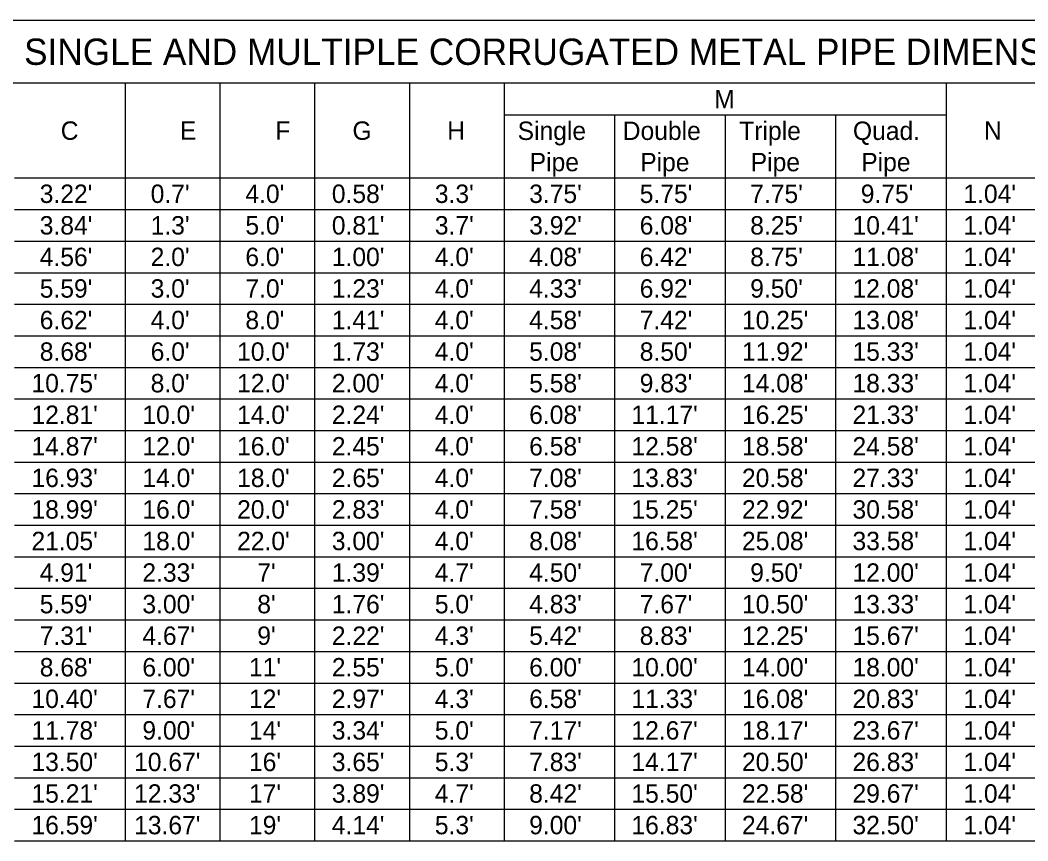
# Model space of a CAD drawing. Extents: x -1.3 to 14.4, y 0 to 6.5.
# Drawn here: x 4.481 to 8.31, y 3.39 to 6.51 of the extents above; entities that cross this region are included whole.
import ezdxf

# ---------------------------------------------------------------- set-up
doc = ezdxf.new("R2010")
doc.units = 0
doc.layers.add('TextNotes', color=7, linetype='Continuous')
doc.layers.add('TextTables', color=7, linetype='Continuous')

msp = doc.modelspace()

# ---------------------------------------------------------------- linework, layer by layer
at = {"layer": 'TextTables'}
msp.add_line((2, 6.51), (13.4, 6.51), dxfattribs=at)
for points in [[(13.4, 6.27), (11.72, 6.27), (10.04, 6.27), (8.36, 6.27), (8, 6.27), (6.32, 6.27), (5.96, 6.27), (5.6, 6.27), (5.24, 6.27), (4.88, 6.27), (4.46, 6.27), (3.98, 6.27), (3.56, 6.27), (3.14, 6.27), (2.84, 6.27), (2.54, 6.27), (2.24, 6.27), (2, 6.27)], [(4.88, 6.27), (4.88, 5.91), (4.88, 5.79), (4.88, 5.67), (4.88, 5.55), (4.88, 5.43), (4.88, 5.31), (4.88, 5.19), (4.88, 5.07), (4.88, 4.95), (4.88, 4.83), (4.88, 4.71), (4.88, 4.59), (4.88, 4.47), (4.88, 4.35), (4.88, 4.23), (4.88, 4.11), (4.88, 3.99), (4.88, 3.87), (4.88, 3.75), (4.88, 3.63), (4.88, 3.51), (4.88, 3.39)], [(5.24, 6.27), (5.24, 5.91), (5.24, 5.79), (5.24, 5.67), (5.24, 5.55), (5.24, 5.43), (5.24, 5.31), (5.24, 5.19), (5.24, 5.07), (5.24, 4.95), (5.24, 4.83), (5.24, 4.71), (5.24, 4.59), (5.24, 4.47), (5.24, 4.35), (5.24, 4.23), (5.24, 4.11), (5.24, 3.99), (5.24, 3.87), (5.24, 3.75), (5.24, 3.63), (5.24, 3.51), (5.24, 3.39)], [(5.6, 6.27), (5.6, 5.91), (5.6, 5.79), (5.6, 5.67), (5.6, 5.55), (5.6, 5.43), (5.6, 5.31), (5.6, 5.19), (5.6, 5.07), (5.6, 4.95), (5.6, 4.83), (5.6, 4.71), (5.6, 4.59), (5.6, 4.47), (5.6, 4.35), (5.6, 4.23), (5.6, 4.11), (5.6, 3.99), (5.6, 3.87), (5.6, 3.75), (5.6, 3.63), (5.6, 3.51), (5.6, 3.39)], [(5.96, 6.27), (5.96, 5.91), (5.96, 5.79), (5.96, 5.67), (5.96, 5.55), (5.96, 5.43), (5.96, 5.31), (5.96, 5.19), (5.96, 5.07), (5.96, 4.95), (5.96, 4.83), (5.96, 4.71), (5.96, 4.59), (5.96, 4.47), (5.96, 4.35), (5.96, 4.23), (5.96, 4.11), (5.96, 3.99), (5.96, 3.87), (5.96, 3.75), (5.96, 3.63), (5.96, 3.51), (5.96, 3.39)], [(6.32, 6.27), (6.32, 6.15), (6.32, 5.91), (6.32, 5.79), (6.32, 5.67), (6.32, 5.55), (6.32, 5.43), (6.32, 5.31), (6.32, 5.19), (6.32, 5.07), (6.32, 4.95), (6.32, 4.83), (6.32, 4.71), (6.32, 4.59), (6.32, 4.47), (6.32, 4.35), (6.32, 4.23), (6.32, 4.11), (6.32, 3.99), (6.32, 3.87), (6.32, 3.75), (6.32, 3.63), (6.32, 3.51), (6.32, 3.39)], [(8, 6.27), (8, 6.15), (8, 5.91), (8, 5.79), (8, 5.67), (8, 5.55), (8, 5.43), (8, 5.31), (8, 5.19), (8, 5.07), (8, 4.95), (8, 4.83), (8, 4.71), (8, 4.59), (8, 4.47), (8, 4.35), (8, 4.23), (8, 4.11), (8, 3.99), (8, 3.87), (8, 3.75), (8, 3.63), (8, 3.51), (8, 3.39)], [(6.32, 6.15), (6.74, 6.15), (7.16, 6.15), (7.58, 6.15), (8, 6.15)], [(6.74, 6.15), (6.74, 5.91), (6.74, 5.79), (6.74, 5.67), (6.74, 5.55), (6.74, 5.43), (6.74, 5.31), (6.74, 5.19), (6.74, 5.07), (6.74, 4.95), (6.74, 4.83), (6.74, 4.71), (6.74, 4.59), (6.74, 4.47), (6.74, 4.35), (6.74, 4.23), (6.74, 4.11), (6.74, 3.99), (6.74, 3.87), (6.74, 3.75), (6.74, 3.63), (6.74, 3.51), (6.74, 3.39)], [(7.16, 6.15), (7.16, 5.91), (7.16, 5.79), (7.16, 5.67), (7.16, 5.55), (7.16, 5.43), (7.16, 5.31), (7.16, 5.19), (7.16, 5.07), (7.16, 4.95), (7.16, 4.83), (7.16, 4.71), (7.16, 4.59), (7.16, 4.47), (7.16, 4.35), (7.16, 4.23), (7.16, 4.11), (7.16, 3.99), (7.16, 3.87), (7.16, 3.75), (7.16, 3.63), (7.16, 3.51), (7.16, 3.39)], [(7.58, 6.15), (7.58, 5.91), (7.58, 5.79), (7.58, 5.67), (7.58, 5.55), (7.58, 5.43), (7.58, 5.31), (7.58, 5.19), (7.58, 5.07), (7.58, 4.95), (7.58, 4.83), (7.58, 4.71), (7.58, 4.59), (7.58, 4.47), (7.58, 4.35), (7.58, 4.23), (7.58, 4.11), (7.58, 3.99), (7.58, 3.87), (7.58, 3.75), (7.58, 3.63), (7.58, 3.51), (7.58, 3.39)], [(4.46, 5.91), (4.88, 5.91), (5.24, 5.91), (5.6, 5.91), (5.96, 5.91), (6.32, 5.91), (6.74, 5.91), (7.16, 5.91), (7.58, 5.91), (8, 5.91), (8.36, 5.91), (9.2, 5.91), (10.04, 5.91), (10.46, 5.91), (10.88, 5.91), (11.3, 5.91), (11.72, 5.91), (12.14, 5.91), (12.56, 5.91), (12.98, 5.91), (13.4, 5.91)], [(4.46, 5.79), (4.88, 5.79), (5.24, 5.79), (5.6, 5.79), (5.96, 5.79), (6.32, 5.79), (6.74, 5.79), (7.16, 5.79), (7.58, 5.79), (8, 5.79), (8.36, 5.79), (9.2, 5.79), (10.04, 5.79), (10.46, 5.79), (10.88, 5.79), (11.3, 5.79), (11.72, 5.79), (12.14, 5.79), (12.56, 5.79), (12.98, 5.79), (13.4, 5.79)], [(4.46, 5.67), (4.88, 5.67), (5.24, 5.67), (5.6, 5.67), (5.96, 5.67), (6.32, 5.67), (6.74, 5.67), (7.16, 5.67), (7.58, 5.67), (8, 5.67), (8.36, 5.67), (9.2, 5.67), (10.04, 5.67), (10.46, 5.67), (10.88, 5.67), (11.3, 5.67), (11.72, 5.67), (12.14, 5.67), (12.56, 5.67), (12.98, 5.67), (13.4, 5.67)], [(4.46, 5.55), (4.88, 5.55), (5.24, 5.55), (5.6, 5.55), (5.96, 5.55), (6.32, 5.55), (6.74, 5.55), (7.16, 5.55), (7.58, 5.55), (8, 5.55), (8.36, 5.55), (9.2, 5.55), (10.04, 5.55), (10.46, 5.55), (10.88, 5.55), (11.3, 5.55), (11.72, 5.55), (12.14, 5.55), (12.56, 5.55), (12.98, 5.55), (13.4, 5.55)], [(4.46, 5.43), (4.88, 5.43), (5.24, 5.43), (5.6, 5.43), (5.96, 5.43), (6.32, 5.43), (6.74, 5.43), (7.16, 5.43), (7.58, 5.43), (8, 5.43), (8.36, 5.43), (9.2, 5.43), (10.04, 5.43), (10.46, 5.43), (10.88, 5.43), (11.3, 5.43), (11.72, 5.43), (12.14, 5.43), (12.56, 5.43), (12.98, 5.43), (13.4, 5.43)], [(4.46, 5.31), (4.88, 5.31), (5.24, 5.31), (5.6, 5.31), (5.96, 5.31), (6.32, 5.31), (6.74, 5.31), (7.16, 5.31), (7.58, 5.31), (8, 5.31), (8.36, 5.31), (9.2, 5.31), (10.04, 5.31), (10.46, 5.31), (10.88, 5.31), (11.3, 5.31), (11.72, 5.31), (12.14, 5.31), (12.56, 5.31), (12.98, 5.31), (13.4, 5.31)], [(4.46, 5.19), (4.88, 5.19), (5.24, 5.19), (5.6, 5.19), (5.96, 5.19), (6.32, 5.19), (6.74, 5.19), (7.16, 5.19), (7.58, 5.19), (8, 5.19), (8.36, 5.19), (9.2, 5.19), (10.04, 5.19), (10.46, 5.19), (10.88, 5.19), (11.3, 5.19), (11.72, 5.19), (12.14, 5.19), (12.56, 5.19), (12.98, 5.19), (13.4, 5.19)], [(4.46, 5.07), (4.88, 5.07), (5.24, 5.07), (5.6, 5.07), (5.96, 5.07), (6.32, 5.07), (6.74, 5.07), (7.16, 5.07), (7.58, 5.07), (8, 5.07), (8.36, 5.07), (9.2, 5.07), (10.04, 5.07), (10.46, 5.07), (10.88, 5.07), (11.3, 5.07), (11.72, 5.07), (12.14, 5.07), (12.56, 5.07), (12.98, 5.07), (13.4, 5.07)], [(4.46, 4.95), (4.88, 4.95), (5.24, 4.95), (5.6, 4.95), (5.96, 4.95), (6.32, 4.95), (6.74, 4.95), (7.16, 4.95), (7.58, 4.95), (8, 4.95), (8.36, 4.95), (9.2, 4.95), (10.04, 4.95), (10.46, 4.95), (10.88, 4.95), (11.3, 4.95), (11.72, 4.95), (12.14, 4.95), (12.56, 4.95), (12.98, 4.95), (13.4, 4.95)], [(4.46, 4.83), (4.88, 4.83), (5.24, 4.83), (5.6, 4.83), (5.96, 4.83), (6.32, 4.83), (6.74, 4.83), (7.16, 4.83), (7.58, 4.83), (8, 4.83), (8.36, 4.83), (9.2, 4.83), (10.04, 4.83), (10.46, 4.83), (10.88, 4.83), (11.3, 4.83), (11.72, 4.83), (12.14, 4.83), (12.56, 4.83), (12.98, 4.83), (13.4, 4.83)], [(4.46, 4.71), (4.88, 4.71), (5.24, 4.71), (5.6, 4.71), (5.96, 4.71), (6.32, 4.71), (6.74, 4.71), (7.16, 4.71), (7.58, 4.71), (8, 4.71), (8.36, 4.71), (9.2, 4.71), (10.04, 4.71), (10.46, 4.71), (10.88, 4.71), (11.3, 4.71), (11.72, 4.71), (12.14, 4.71), (12.56, 4.71), (12.98, 4.71), (13.4, 4.71)], [(4.46, 4.59), (4.88, 4.59), (5.24, 4.59), (5.6, 4.59), (5.96, 4.59), (6.32, 4.59), (6.74, 4.59), (7.16, 4.59), (7.58, 4.59), (8, 4.59), (8.36, 4.59), (9.2, 4.59), (10.04, 4.59), (10.46, 4.59), (10.88, 4.59), (11.3, 4.59), (11.72, 4.59), (12.14, 4.59), (12.56, 4.59), (12.98, 4.59), (13.4, 4.59)], [(4.46, 4.47), (4.88, 4.47), (5.24, 4.47), (5.6, 4.47), (5.96, 4.47), (6.32, 4.47), (6.74, 4.47), (7.16, 4.47), (7.58, 4.47), (8, 4.47), (8.36, 4.47), (9.2, 4.47), (10.04, 4.47), (10.46, 4.47), (10.88, 4.47), (11.3, 4.47), (11.72, 4.47), (12.14, 4.47), (12.56, 4.47), (12.98, 4.47), (13.4, 4.47)], [(4.46, 4.47), (4.88, 4.47), (5.24, 4.47), (5.6, 4.47), (5.96, 4.47), (6.32, 4.47), (6.74, 4.47), (7.16, 4.47), (7.58, 4.47), (8, 4.47), (8.36, 4.47), (9.2, 4.47), (10.04, 4.47), (10.46, 4.47), (10.88, 4.47), (11.3, 4.47), (11.72, 4.47), (12.14, 4.47), (12.56, 4.47), (12.98, 4.47), (13.4, 4.47)], [(4.46, 4.35), (4.88, 4.35), (5.24, 4.35), (5.6, 4.35), (5.96, 4.35), (6.32, 4.35), (6.74, 4.35), (7.16, 4.35), (7.58, 4.35), (8, 4.35), (8.36, 4.35), (9.2, 4.35), (10.04, 4.35), (10.46, 4.35), (10.88, 4.35), (11.3, 4.35), (11.72, 4.35), (12.14, 4.35), (12.56, 4.35), (12.98, 4.35), (13.4, 4.35)], [(4.46, 4.23), (4.88, 4.23), (5.24, 4.23), (5.6, 4.23), (5.96, 4.23), (6.32, 4.23), (6.74, 4.23), (7.16, 4.23), (7.58, 4.23), (8, 4.23), (8.36, 4.23), (9.2, 4.23), (10.04, 4.23), (10.46, 4.23), (10.88, 4.23), (11.3, 4.23), (11.72, 4.23), (12.14, 4.23), (12.56, 4.23), (12.98, 4.23), (13.4, 4.23)], [(4.46, 4.11), (4.88, 4.11), (5.24, 4.11), (5.6, 4.11), (5.96, 4.11), (6.32, 4.11), (6.74, 4.11), (7.16, 4.11), (7.58, 4.11), (8, 4.11), (8.36, 4.11), (9.2, 4.11), (10.04, 4.11), (10.46, 4.11), (10.88, 4.11), (11.3, 4.11), (11.72, 4.11), (12.14, 4.11), (12.56, 4.11), (12.98, 4.11), (13.4, 4.11)], [(4.46, 3.99), (4.88, 3.99), (5.24, 3.99), (5.6, 3.99), (5.96, 3.99), (6.32, 3.99), (6.74, 3.99), (7.16, 3.99), (7.58, 3.99), (8, 3.99), (8.36, 3.99), (9.2, 3.99), (10.04, 3.99), (10.46, 3.99), (10.88, 3.99), (11.3, 3.99), (11.72, 3.99), (12.14, 3.99), (12.56, 3.99), (12.98, 3.99), (13.4, 3.99)], [(4.46, 3.87), (4.88, 3.87), (5.24, 3.87), (5.6, 3.87), (5.96, 3.87), (6.32, 3.87), (6.74, 3.87), (7.16, 3.87), (7.58, 3.87), (8, 3.87), (8.36, 3.87), (9.2, 3.87), (10.04, 3.87), (10.46, 3.87), (10.88, 3.87), (11.3, 3.87), (11.72, 3.87), (12.14, 3.87), (12.56, 3.87), (12.98, 3.87), (13.4, 3.87)], [(4.46, 3.75), (4.88, 3.75), (5.24, 3.75), (5.6, 3.75), (5.96, 3.75), (6.32, 3.75), (6.74, 3.75), (7.16, 3.75), (7.58, 3.75), (8, 3.75), (8.36, 3.75), (9.2, 3.75), (10.04, 3.75), (10.46, 3.75), (10.88, 3.75), (11.3, 3.75), (11.72, 3.75), (12.14, 3.75), (12.56, 3.75), (12.98, 3.75), (13.4, 3.75)], [(4.46, 3.63), (4.88, 3.63), (5.24, 3.63), (5.6, 3.63), (5.96, 3.63), (6.32, 3.63), (6.74, 3.63), (7.16, 3.63), (7.58, 3.63), (8, 3.63), (8.36, 3.63), (9.2, 3.63), (10.04, 3.63), (10.46, 3.63), (10.88, 3.63), (11.3, 3.63), (11.72, 3.63), (12.14, 3.63), (12.56, 3.63), (12.98, 3.63), (13.4, 3.63)], [(4.46, 3.51), (4.88, 3.51), (5.24, 3.51), (5.6, 3.51), (5.96, 3.51), (6.32, 3.51), (6.74, 3.51), (7.16, 3.51), (7.58, 3.51), (8, 3.51), (8.36, 3.51), (9.2, 3.51), (10.04, 3.51), (10.46, 3.51), (10.88, 3.51), (11.3, 3.51), (11.72, 3.51), (12.14, 3.51), (12.56, 3.51), (12.98, 3.51), (13.4, 3.51)], [(4.46, 3.39), (4.88, 3.39), (5.24, 3.39), (5.6, 3.39), (5.96, 3.39), (6.32, 3.39), (6.74, 3.39), (7.16, 3.39), (7.58, 3.39), (8, 3.39), (8.36, 3.39), (9.2, 3.39), (10.04, 3.39), (10.46, 3.39), (10.88, 3.39), (11.3, 3.39), (11.72, 3.39), (12.14, 3.39), (12.56, 3.39), (12.98, 3.39), (13.4, 3.39)]]:
    msp.add_lwpolyline(points, dxfattribs=at)

# ---------------------------------------------------------------- texts
at = {"layer": 'TextNotes'}
for s, height, p in [('SINGLE AND MULTIPLE CORRUGATED METAL PIPE DIMENSIONS AND QUANTITIES', 0.1, (4.4959, 6.34)), ('M', 0.07, (7.1183, 6.175)), ('Single', 0.07, (6.3714, 6.0545)), ('Double', 0.07, (6.7709, 6.0545)), ('Triple', 0.07, (7.2137, 6.0545)), ('Quad.', 0.07, (7.6457, 6.0545)), ('C', 0.07, (4.6352, 6.055)), ('E', 0.07, (5.0882, 6.055)), ('F', 0.07, (5.4503, 6.055)), ('G', 0.07, (5.7438, 6.055)), ('H', 0.07, (6.1037, 6.055)), ('N', 0.07, (8.1438, 6.055)), ('Pipe', 0.07, (6.4173, 5.9355)), ('Pipe', 0.07, (6.8373, 5.9355)), ('Pipe', 0.07, (7.2573, 5.9355)), ('Pipe', 0.07, (7.6773, 5.9355))]:
    msp.add_text(s, height=height, dxfattribs=at).set_placement(p)
for s, p in [("3.22'", (4.5554, 5.815)), ("0.7'", (4.9769, 5.815)), ("4.0'", (5.3369, 5.815)), ("0.58'", (5.6654, 5.815)), ("3.3'", (6.0569, 5.815)), ("3.75'", (6.4154, 5.815)), ("5.75'", (6.8354, 5.815)), ("7.75'", (7.2554, 5.815)), ("9.75'", (7.6754, 5.815)), ("1.04'", (8.0654, 5.815)), ("3.84'", (4.5554, 5.695)), ("1.3'", (4.9769, 5.695)), ("5.0'", (5.3369, 5.695)), ("0.81'", (5.6654, 5.695)), ("3.7'", (6.0569, 5.695)), ("3.92'", (6.4154, 5.695)), ("6.08'", (6.8354, 5.695)), ("8.25'", (7.2554, 5.695)), ("10.41'", (7.644, 5.695)), ("1.04'", (8.0654, 5.695)), ("4.56'", (4.5554, 5.575)), ("2.0'", (4.9769, 5.575)), ("6.0'", (5.3369, 5.575)), ("1.00'", (5.6654, 5.575)), ("4.0'", (6.0569, 5.575)), ("4.08'", (6.4154, 5.575)), ("6.42'", (6.8354, 5.575)), ("8.75'", (7.2554, 5.575)), ("11.08'", (7.644, 5.575)), ("1.04'", (8.0654, 5.575)), ("5.59'", (4.5554, 5.455)), ("3.0'", (4.9769, 5.455)), ("7.0'", (5.3369, 5.455)), ("1.23'", (5.6654, 5.455)), ("4.0'", (6.0569, 5.455)), ("4.33'", (6.4154, 5.455)), ("6.92'", (6.8354, 5.455)), ("9.50'", (7.2554, 5.455)), ("12.08'", (7.644, 5.455)), ("1.04'", (8.0654, 5.455)), ("6.62'", (4.5554, 5.335)), ("4.0'", (4.9769, 5.335)), ("8.0'", (5.3369, 5.335)), ("1.41'", (5.6654, 5.335)), ("4.0'", (6.0569, 5.335)), ("4.58'", (6.4154, 5.335)), ("7.42'", (6.8354, 5.335)), ("10.25'", (7.224, 5.335)), ("13.08'", (7.644, 5.335)), ("1.04'", (8.0654, 5.335)), ("8.68'", (4.5554, 5.215)), ("6.0'", (4.9769, 5.215)), ("10.0'", (5.3054, 5.215)), ("1.73'", (5.6654, 5.215)), ("4.0'", (6.0569, 5.215)), ("5.08'", (6.4154, 5.215)), ("8.50'", (6.8354, 5.215)), ("11.92'", (7.224, 5.215)), ("15.33'", (7.644, 5.215)), ("1.04'", (8.0654, 5.215)), ("10.75'", (4.524, 5.095)), ("8.0'", (4.9769, 5.095)), ("12.0'", (5.3054, 5.095)), ("2.00'", (5.6654, 5.095)), ("4.0'", (6.0569, 5.095)), ("5.58'", (6.4154, 5.095)), ("9.83'", (6.8354, 5.095)), ("14.08'", (7.224, 5.095)), ("18.33'", (7.644, 5.095)), ("1.04'", (8.0654, 5.095)), ("12.81'", (4.524, 4.975)), ("10.0'", (4.9454, 4.975)), ("14.0'", (5.3054, 4.975)), ("2.24'", (5.6654, 4.975)), ("4.0'", (6.0569, 4.975)), ("6.08'", (6.4154, 4.975)), ("11.17'", (6.804, 4.975)), ("16.25'", (7.224, 4.975)), ("21.33'", (7.644, 4.975)), ("1.04'", (8.0654, 4.975)), ("14.87'", (4.524, 4.855)), ("12.0'", (4.9454, 4.855)), ("16.0'", (5.3054, 4.855)), ("2.45'", (5.6654, 4.855)), ("4.0'", (6.0569, 4.855)), ("6.58'", (6.4154, 4.855)), ("12.58'", (6.804, 4.855)), ("18.58'", (7.224, 4.855)), ("24.58'", (7.644, 4.855)), ("1.04'", (8.0654, 4.855)), ("16.93'", (4.524, 4.735)), ("14.0'", (4.9454, 4.735)), ("18.0'", (5.3054, 4.735)), ("2.65'", (5.6654, 4.735)), ("4.0'", (6.0569, 4.735)), ("7.08'", (6.4154, 4.735)), ("13.83'", (6.804, 4.735)), ("20.58'", (7.224, 4.735)), ("27.33'", (7.644, 4.735)), ("1.04'", (8.0654, 4.735)), ("18.99'", (4.524, 4.615)), ("16.0'", (4.9454, 4.615)), ("20.0'", (5.3054, 4.615)), ("2.83'", (5.6654, 4.615)), ("4.0'", (6.0569, 4.615)), ("7.58'", (6.4154, 4.615)), ("15.25'", (6.804, 4.615)), ("22.92'", (7.224, 4.615)), ("30.58'", (7.644, 4.615)), ("1.04'", (8.0654, 4.615)), ("21.05'", (4.524, 4.495)), ("18.0'", (4.9454, 4.495)), ("22.0'", (5.3054, 4.495)), ("3.00'", (5.6654, 4.495)), ("4.0'", (6.0569, 4.495)), ("8.08'", (6.4154, 4.495)), ("16.58'", (6.804, 4.495)), ("25.08'", (7.224, 4.495)), ("33.58'", (7.644, 4.495)), ("1.04'", (8.0654, 4.495)), ("4.91'", (4.5554, 4.375)), ("2.33'", (4.9454, 4.375)), ("7'", (5.3821, 4.375)), ("1.39'", (5.6654, 4.375)), ("4.7'", (6.0569, 4.375)), ("4.50'", (6.4154, 4.375)), ("7.00'", (6.8354, 4.375)), ("9.50'", (7.2554, 4.375)), ("12.00'", (7.644, 4.375)), ("1.04'", (8.0654, 4.375)), ("5.59'", (4.5554, 4.255)), ("3.00'", (4.9454, 4.255)), ("8'", (5.3821, 4.255)), ("1.76'", (5.6654, 4.255)), ("5.0'", (6.0569, 4.255)), ("4.83'", (6.4154, 4.255)), ("7.67'", (6.8354, 4.255)), ("10.50'", (7.224, 4.255)), ("13.33'", (7.644, 4.255)), ("1.04'", (8.0654, 4.255)), ("7.31'", (4.5554, 4.135)), ("4.67'", (4.9454, 4.135)), ("9'", (5.3821, 4.135)), ("2.22'", (5.6654, 4.135)), ("4.3'", (6.0569, 4.135)), ("5.42'", (6.4154, 4.135)), ("8.83'", (6.8354, 4.135)), ("12.25'", (7.224, 4.135)), ("15.67'", (7.644, 4.135)), ("1.04'", (8.0654, 4.135)), ("8.68'", (4.5554, 4.015)), ("6.00'", (4.9454, 4.015)), ("11'", (5.3506, 4.015)), ("2.55'", (5.6654, 4.015)), ("5.0'", (6.0569, 4.015)), ("6.00'", (6.4154, 4.015)), ("10.00'", (6.804, 4.015)), ("14.00'", (7.224, 4.015)), ("18.00'", (7.644, 4.015)), ("1.04'", (8.0654, 4.015)), ("10.40'", (4.524, 3.895)), ("7.67'", (4.9454, 3.895)), ("12'", (5.3506, 3.895)), ("2.97'", (5.6654, 3.895)), ("4.3'", (6.0569, 3.895)), ("6.58'", (6.4154, 3.895)), ("11.33'", (6.804, 3.895)), ("16.08'", (7.224, 3.895)), ("20.83'", (7.644, 3.895)), ("1.04'", (8.0654, 3.895)), ("11.78'", (4.524, 3.775)), ("9.00'", (4.9454, 3.775)), ("14'", (5.3506, 3.775)), ("3.34'", (5.6654, 3.775)), ("5.0'", (6.0569, 3.775)), ("7.17'", (6.4154, 3.775)), ("12.67'", (6.804, 3.775)), ("18.17'", (7.224, 3.775)), ("23.67'", (7.644, 3.775)), ("1.04'", (8.0654, 3.775)), ("13.50'", (4.524, 3.655)), ("10.67'", (4.914, 3.655)), ("16'", (5.3506, 3.655)), ("3.65'", (5.6654, 3.655)), ("5.3'", (6.0569, 3.655)), ("7.83'", (6.4154, 3.655)), ("14.17'", (6.804, 3.655)), ("20.50'", (7.224, 3.655)), ("26.83'", (7.644, 3.655)), ("1.04'", (8.0654, 3.655)), ("15.21'", (4.524, 3.535)), ("12.33'", (4.914, 3.535)), ("17'", (5.3506, 3.535)), ("3.89'", (5.6654, 3.535)), ("4.7'", (6.0569, 3.535)), ("8.42'", (6.4154, 3.535)), ("15.50'", (6.804, 3.535)), ("22.58'", (7.224, 3.535)), ("29.67'", (7.644, 3.535)), ("1.04'", (8.0654, 3.535)), ("16.59'", (4.524, 3.415)), ("13.67'", (4.914, 3.415)), ("19'", (5.3506, 3.415)), ("4.14'", (5.6654, 3.415)), ("5.3'", (6.0569, 3.415)), ("9.00'", (6.4154, 3.415)), ("16.83'", (6.804, 3.415)), ("24.67'", (7.224, 3.415)), ("32.50'", (7.644, 3.415)), ("1.04'", (8.0654, 3.415))]:
    msp.add_text(s, height=0.07, rotation=0, dxfattribs=at).set_placement(p)

doc.saveas('drawing.dxf')
